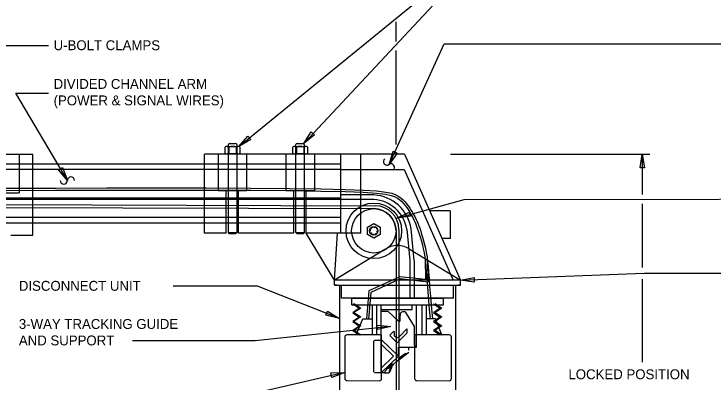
# Model space of a CAD drawing. Extents: x 1299104.6 to 1299141.4, y 239713.3 to 239735.3.
# Drawn here: x 1299120.38 to 1299128.87, y 239725.82 to 239730.29 of the extents above; entities that cross this region are included whole.
import ezdxf

# ---------------------------------------------------------------- set-up
doc = ezdxf.new("R2010")
doc.units = 0
for name, color, linetype in [('Default', 7, 'Continuous'), ('DIM TXT', 7, 'Continuous'), ('Level 3', 7, 'Continuous'), ('Level 6', 7, 'Continuous'), ('Level 8', 7, 'Continuous')]:
    doc.layers.add(name, color=color, linetype=linetype)

# ---------------------------------------------------------------- blocks, each defined once
blk = doc.blocks.new('SPRING')
at = {"layer": 'Default'}
for p, q in [((-0.4, 4), (0.8, 3.2)), ((0.8, 3.2), (-0.4, 2.4)), ((-0.4, 2.4), (0.8, 1.6)), ((0.8, 1.6), (-0.4, 0.8)), ((-0.4, 0.8), (0.8, 0))]:
    blk.add_line(p, q, dxfattribs=at)
blk = doc.blocks.new('HBOLT06T')
at = {"layer": 'Default'}
blk.add_lwpolyline([(0, 2.6), (2.25, 1.3), (2.25, -1.3), (0, -2.6), (-2.25, -1.3), (-2.25, 1.3)], close=True, dxfattribs=at)
blk.add_circle((0, 0), 1.5, dxfattribs=at)
for start, end in [(159.2494, 186.8604), (113.1597, 137.2755), (66.2738, 91.4347), (25.0164, 44.5428), (340.6969, 5.1062), (206.8165, 228.1121), (247.7162, 270.4735), (295.5824, 320.2457)]:
    blk.add_arc((0, 0), 1.27, start, end, dxfattribs=at)
blk = doc.blocks.new('BOLTS')
at = {"layer": 'Default'}
for p, q in [((-1.1, 17.81), (1.1, 17.81)), ((-1.95, 16.76), (1.95, 16.76)), ((-1.5, 0), (-1.5, 17.41)), ((-1.3, 16.52), (-1.3, 14.31)), ((1.3, 16.52), (1.3, 14.31)), ((1.5, 17.41), (1.5, 0)), ((1.95, 14.07), (-1.95, 14.07)), ((-1.5, -14.24), (-1.5, 0)), ((1.5, 0), (1.5, -14.24)), ((-1.5, -14.24), (1.5, -14.24)), ((-1.1, -14.64), (-1.5, -14.24)), ((1.1, -14.64), (-1.1, -14.64)), ((1.5, -14.24), (1.1, -14.64))]:
    blk.add_line(p, q, dxfattribs=at)
for points in [[(-2.6, 14.31), (-2.6, 16.52)], [(2.6, 16.52), (2.6, 14.31)]]:
    blk.add_lwpolyline(points, dxfattribs=at)
for centre, radius, start, end in [((-1.1, 17.41), 0.4, 90, 180), ((1.1, 17.41), 0.4, 0, 90), ((-1.95, 15.76), 1, 49.4687, 130.5313), ((0, 13.12), 3.64, 69.0802, 110.9198), ((1.95, 15.76), 1, 49.4687, 130.5314), ((-1.95, 15.07), 1, 229.4687, 310.5314), ((0, 17.71), 3.64, 249.0802, 290.9198), ((1.95, 15.07), 1, 229.4687, 310.5313)]:
    blk.add_arc(centre, radius, start, end, dxfattribs=at)

msp = doc.modelspace()

# ---------------------------------------------------------------- linework, layer by layer
at = {"layer": 'Level 3'}
for p, q in [((1299118.1826, 239728.5854), (1299120.6126, 239728.5854)), ((1299120.4495, 239728.5854), (1299120.4495, 239728.1129)), ((1299120.6126, 239727.5999), (1299120.6126, 239728.5854)), ((1299122.697, 239728.4639), (1299122.697, 239728.5854)), ((1299125.127, 239728.5854), (1299122.697, 239728.5854)), ((1299122.8625, 239728.5854), (1299122.8625, 239728.1399)), ((1299123.2093, 239728.5854), (1299123.2093, 239728.1399)), ((1299123.686, 239728.5854), (1299123.686, 239728.1399)), ((1299124.0328, 239728.5854), (1299124.0328, 239728.1399)), ((1299124.3548, 239727.6269), (1299124.3548, 239728.5854)), ((1299124.5978, 239727.6269), (1299124.5978, 239728.5854)), ((1299125.127, 239728.5854), (1299125.8054, 239727.0532)), ((1299122.697, 239728.4639), (1299120.6126, 239728.4639)), ((1299122.697, 239727.6269), (1299122.697, 239728.4639)), ((1299120.098, 239728.1129), (1299120.4495, 239728.1129)), ((1299123.2093, 239728.1399), (1299122.8625, 239728.1399)), ((1299122.9616, 239727.6269), (1299122.9616, 239728.1399)), ((1299123.1101, 239727.6269), (1299123.1101, 239728.1399)), ((1299124.0328, 239728.1399), (1299123.686, 239728.1399)), ((1299123.7851, 239727.6269), (1299123.7851, 239728.1399)), ((1299123.9336, 239728.1399), (1299123.7851, 239728.1399)), ((1299123.9336, 239727.6269), (1299123.9336, 239728.1399)), ((1299125.6813, 239727.8955), (1299125.4324, 239727.8955)), ((1299125.6845, 239727.5594), (1299125.6845, 239727.8969)), ((1299124.3548, 239727.8159), (1299122.697, 239727.8159)), ((1299122.697, 239727.7484), (1299120.6126, 239727.7484)), ((1299124.3548, 239727.7484), (1299122.697, 239727.7484)), ((1299123.9336, 239727.7484), (1299123.7851, 239727.7484)), ((1299120.348, 239727.5999), (1299120.6126, 239727.5999)), ((1299122.9616, 239727.6269), (1299122.697, 239727.6269)), ((1299123.7851, 239727.6269), (1299123.1101, 239727.6269)), ((1299124.2772, 239727.0532), (1299123.9336, 239727.6269)), ((1299124.5978, 239727.6269), (1299123.9336, 239727.6269)), ((1299124.2772, 239727.0532), (1299124.315, 239727.6269)), ((1299125.6845, 239727.5594), (1299125.5813, 239727.5594)), ((1299124.8873, 239727.4277), (1299124.2772, 239727.0532)), ((1299125.1953, 239727.4277), (1299125.8054, 239727.0532)), ((1299125.2438, 239727.2948), (1299125.2438, 239726.8346)), ((1299124.2772, 239726.9924), (1299124.2772, 239727.0532)), ((1299125.8054, 239727.0532), (1299124.2772, 239727.0532)), ((1299124.2772, 239726.9924), (1299125.8054, 239726.9924)), ((1299124.3042, 239726.9924), (1299124.2772, 239726.9924)), ((1299124.3359, 239726.9924), (1299124.3359, 239725.2509)), ((1299124.3359, 239726.9924), (1299125.7467, 239726.9924)), ((1299124.3602, 239726.8358), (1299124.3602, 239726.9924)), ((1299125.7224, 239726.8358), (1299125.7224, 239726.9924)), ((1299125.7467, 239726.9924), (1299125.7467, 239725.2509)), ((1299125.8054, 239726.9924), (1299125.7784, 239726.9924)), ((1299125.8054, 239726.9924), (1299125.8054, 239727.0532)), ((1299125.7224, 239726.8358), (1299124.3602, 239726.8358)), ((1299124.4856, 239726.7536), (1299124.4856, 239726.8346)), ((1299124.4856, 239726.8346), (1299125.6007, 239726.8346)), ((1299125.6007, 239726.7536), (1299125.6007, 239726.8346)), ((1299124.4856, 239726.7536), (1299125.6007, 239726.7536)), ((1299124.7343, 239726.7536), (1299124.7343, 239726.3904)), ((1299124.7883, 239726.7536), (1299124.7883, 239726.3904)), ((1299124.842, 239726.6996), (1299124.842, 239726.7536)), ((1299124.8433, 239725.9301), (1299124.8433, 239726.7536)), ((1299125.22, 239726.6996), (1299125.22, 239726.7536)), ((1299125.274, 239726.2406), (1299125.274, 239726.7536)), ((1299125.3355, 239726.7536), (1299125.3355, 239726.3904)), ((1299125.3895, 239726.7536), (1299125.3895, 239726.3904)), ((1299124.842, 239726.6996), (1299125.22, 239726.6996)), ((1299124.927, 239726.6726), (1299124.8433, 239726.6726)), ((1299124.927, 239726.6726), (1299125.0594, 239726.555)), ((1299125.247, 239726.4944), (1299125.1501, 239726.6485)), ((1299124.5417, 239726.3904), (1299124.6208, 239726.5839)), ((1299124.6208, 239726.5839), (1299124.7343, 239726.5839)), ((1299125.0728, 239726.561), (1299125.0728, 239726.6371)), ((1299125.503, 239726.5839), (1299125.3895, 239726.5839)), ((1299125.5821, 239726.3904), (1299125.503, 239726.5839)), ((1299125.247, 239726.2676), (1299125.247, 239726.4944)), ((1299124.8481, 239726.3904), (1299124.4285, 239726.3904)), ((1299124.8481, 239725.8613), (1299124.8481, 239726.3904)), ((1299124.9521, 239726.3914), (1299124.9924, 239726.433)), ((1299124.9924, 239726.433), (1299125.0005, 239726.433)), ((1299125.0005, 239726.433), (1299125.0005, 239726.3856)), ((1299125.0462, 239726.3003), (1299125.1553, 239726.4131)), ((1299125.0651, 239726.3703), (1299125.1562, 239726.4644)), ((1299125.1562, 239726.4644), (1299125.1553, 239726.4131)), ((1299125.6693, 239726.3904), (1299125.2498, 239726.3904)), ((1299125.2498, 239726.3904), (1299125.2498, 239725.8632)), ((1299124.4015, 239726.3634), (1299124.4015, 239725.8632)), ((1299124.7556, 239725.9382), (1299124.7556, 239726.3135)), ((1299124.8433, 239726.3216), (1299124.7637, 239726.3216)), ((1299124.8433, 239726.3351), (1299125.0526, 239726.1326)), ((1299124.9523, 239726.38), (1299125.0348, 239726.3002)), ((1299125.6963, 239725.8613), (1299125.6963, 239726.3634)), ((1299124.8433, 239726.2788), (1299124.9944, 239726.1326)), ((1299125.0526, 239726.2406), (1299125.274, 239726.2406)), ((1299125.0526, 239726.1326), (1299125.0526, 239726.2406)), ((1299125.1795, 239726.2069), (1299125.1795, 239726.2406)), ((1299125.247, 239726.2676), (1299125.274, 239726.2406)), ((1299124.8433, 239725.9865), (1299124.9944, 239726.1326)), ((1299124.8433, 239725.9301), (1299125.0526, 239726.1326)), ((1299124.8433, 239725.9301), (1299124.7637, 239725.9301)), ((1299124.8825, 239725.9301), (1299124.8433, 239725.9301)), ((1299124.8825, 239725.9301), (1299124.9365, 239725.9301)), ((1299124.4284, 239725.8362), (1299124.8209, 239725.8343)), ((1299125.2766, 239725.8362), (1299125.6692, 239725.8343))]:
    msp.add_line(p, q, dxfattribs=at)
for points in [[(1299120.2912, 239728.1707), (1299120.888, 239728.1728), (1299121.5073, 239728.1743), (1299122.1252, 239728.1749), (1299122.7179, 239728.1745), (1299123.2615, 239728.1727), (1299123.732, 239728.1693), (1299124.1117, 239728.1641), (1299124.4063, 239728.1571), (1299124.6278, 239728.1482), (1299124.7881, 239728.1375), (1299124.8994, 239728.1248), (1299124.974, 239728.1099), (1299125.0235, 239728.0922), (1299125.058, 239728.0722), (1299125.0866, 239728.0509), (1299125.1122, 239728.0282), (1299125.1355, 239728.0042), (1299125.1565, 239727.9793), (1299125.1756, 239727.9538), (1299125.193, 239727.9279), (1299125.209, 239727.9021), (1299125.2238, 239727.8765), (1299125.2377, 239727.8512), (1299125.2509, 239727.8258), (1299125.2636, 239727.7999), (1299125.2759, 239727.7732), (1299125.2878, 239727.7453), (1299125.2997, 239727.7159), (1299125.3114, 239727.6846), (1299125.3233, 239727.6511), (1299125.3354, 239727.6149), (1299125.3475, 239727.5759), (1299125.3595, 239727.5342), (1299125.371, 239727.4896), (1299125.3818, 239727.4422), (1299125.3917, 239727.3921), (1299125.4004, 239727.339), (1299125.4077, 239727.2832), (1299125.4136, 239727.2239), (1299125.4188, 239727.1569), (1299125.4245, 239727.077), (1299125.4315, 239726.9789), (1299125.4409, 239726.8573), (1299125.4537, 239726.7071), (1299125.4653, 239726.5839)], [(1299120.2913, 239728.1437), (1299120.8881, 239728.1458), (1299121.5073, 239728.1473), (1299122.1252, 239728.1479), (1299122.7179, 239728.1475), (1299123.2614, 239728.1457), (1299123.7318, 239728.1423), (1299124.1112, 239728.1371), (1299124.4054, 239728.1301), (1299124.6263, 239728.1213), (1299124.7857, 239728.1106), (1299124.8952, 239728.0981), (1299124.9668, 239728.0838), (1299125.0121, 239728.0676), (1299125.0431, 239728.0497), (1299125.0695, 239728.0299), (1299125.0936, 239728.0086), (1299125.1154, 239727.9861), (1299125.1354, 239727.9625), (1299125.1536, 239727.9381), (1299125.1703, 239727.9133), (1299125.1858, 239727.8882), (1299125.2003, 239727.8632), (1299125.2139, 239727.8385), (1299125.2268, 239727.8136), (1299125.2392, 239727.7883), (1299125.2512, 239727.7622), (1299125.2629, 239727.735), (1299125.2745, 239727.7061), (1299125.2861, 239727.6754), (1299125.2978, 239727.6423), (1299125.3097, 239727.6066), (1299125.3216, 239727.5682), (1299125.3334, 239727.5271), (1299125.3447, 239727.4832), (1299125.3554, 239727.4366), (1299125.3651, 239727.3872), (1299125.3737, 239727.3351), (1299125.3809, 239727.2801), (1299125.3867, 239727.2215), (1299125.3919, 239727.1549), (1299125.3975, 239727.075), (1299125.4046, 239726.9769), (1299125.414, 239726.8551), (1299125.4269, 239726.7046), (1299125.4382, 239726.5839)], [(1299125.3778, 239727.3037), (1299125.3809, 239727.0623), (1299125.0713, 239727.0967), (1299124.693, 239726.9249), (1299124.6645, 239726.5839)], [(1299125.4048, 239727.3057), (1299125.4083, 239727.0321), (1299125.0757, 239727.069), (1299124.7186, 239726.9069), (1299124.6916, 239726.5839)]]:
    msp.add_lwpolyline(points, dxfattribs=at)
for centre, radius, start, end in [((1299124.7544, 239727.6536), 0.27, 0, 89.81051), ((1299125.0413, 239727.1931), 0.2806, 56.70764, 123.29236), ((1299125.113, 239726.6321), 0.0405, 23.81865, 187.13136), ((1299125.0647, 239726.561), 0.0081, 228.36646, 0), ((1299124.4285, 239726.3634), 0.027, 90, 180), ((1299124.9579, 239726.3858), 0.0081, 135.93919, 225.93919), ((1299125.6693, 239726.3634), 0.027, 0, 90), ((1299124.7637, 239726.3135), 0.0081, 90, 180), ((1299125.0382, 239726.4009), 0.0407, 202.08979, 311.37571), ((1299125.0404, 239726.306), 0.0081, 225.93919, 315.93919), ((1299124.4285, 239725.8632), 0.027, 180, 269.7176), ((1299124.8211, 239725.8613), 0.027, 269.7176, 0), ((1299125.2768, 239725.8632), 0.027, 180, 269.7176), ((1299125.6693, 239725.8613), 0.027, 269.7176, 0)]:
    msp.add_arc(centre, radius, start, end, dxfattribs=at)
for points in [[(1299125.031, 239726.0677), (1299125.1585, 239726.1631), (1299125.1795, 239726.2069), (1299124.9642, 239726.0243), (1299125.1792, 239726.1826)], [(1299125.031, 239726.0685), (1299124.9707, 239726.0119), (1299124.9525, 239725.9826), (1299124.9409, 239725.9543), (1299124.9365, 239725.9301), (1299125.0007, 239726.0403), (1299124.9365, 239725.9301)], [(1299124.8825, 239725.9301), (1299124.9337, 239726.0166), (1299125.031, 239726.0677), (1299124.8825, 239725.9301), (1299124.9798, 239726.0477)]]:
    msp.add_open_spline(points, degree=3, dxfattribs=at)
at = {"layer": 'Level 6'}
for p, q in [((1299120.6126, 239728.4639), (1299118.9548, 239728.4639)), ((1299124.3548, 239728.4639), (1299122.697, 239728.4639)), ((1299120.6126, 239728.3964), (1299118.9548, 239728.3964)), ((1299122.697, 239728.3964), (1299120.6126, 239728.3964)), ((1299124.3548, 239728.3964), (1299122.697, 239728.3964)), ((1299124.3548, 239728.3964), (1299125.1221, 239728.3964)), ((1299125.1221, 239728.3964), (1299125.7168, 239727.0532)), ((1299124.7549, 239728.0887), (1299124.3548, 239728.0887)), ((1299124.3548, 239728.0482), (1299118.9548, 239728.0482)), ((1299124.3548, 239728.0347), (1299118.9548, 239728.0347)), ((1299124.7549, 239728.0347), (1299124.3548, 239728.0347)), ((1299117.9141, 239727.98), (1299124.7722, 239727.9573)), ((1299117.9309, 239727.9462), (1299124.7553, 239727.9236)), ((1299120.6126, 239727.8159), (1299118.9548, 239727.8159)), ((1299122.697, 239727.8159), (1299120.6126, 239727.8159)), ((1299120.6126, 239727.7484), (1299118.9548, 239727.7484)), ((1299125.0582, 239727.6704), (1299125.0582, 239724.762)), ((1299125.1558, 239727.6737), (1299125.1898, 239727.2948)), ((1299125.2438, 239727.2948), (1299125.2066, 239727.6776)), ((1299125.0244, 239727.6536), (1299125.0244, 239724.6609)), ((1299125.1898, 239727.2948), (1299125.1898, 239726.8346))]:
    msp.add_line(p, q, dxfattribs=at)
for radius in [0.3375, 0.27]:
    msp.add_circle((1299124.7544, 239727.6536), radius, dxfattribs=at)
for centre, radius, start, end in [((1299124.7282, 239727.6056), 0.4838, 8.5622, 86.82966), ((1299124.7254, 239727.5989), 0.4368, 9.86195, 86.12318), ((1299124.7713, 239727.6704), 0.2869, 0, 89.81051)]:
    msp.add_arc(centre, radius, start, end, dxfattribs=at)
at = {"layer": 'Level 8'}
for p, q in [((1299125.0244, 239729.9525), (1299125.0244, 239730.1923)), ((1299125.0244, 239728.7033), (1299125.0244, 239729.8445)), ((1299125.6871, 239728.5854), (1299128.1042, 239728.5854)), ((1299128.0143, 239728.5854), (1299128.0143, 239728.0942)), ((1299128.0143, 239727.9795), (1299128.0143, 239727.2073)), ((1299128.0143, 239727.0667), (1299128.0143, 239726.0593))]:
    msp.add_line(p, q, dxfattribs=at)
for points in [[(1299123.1134, 239728.6774), (1299123.1134, 239728.6774), (1299126.2852, 239731.2629), (1299132.0119, 239731.2629)], [(1299123.9042, 239728.7118), (1299126.2852, 239731.2629), (1299132.0486, 239731.2629)], [(1299119.5029, 239728.6996), (1299119.5029, 239728.6996), (1299120.1241, 239729.9022), (1299120.793, 239729.9022)], [(1299120.2704, 239728.7139), (1299120.1241, 239729.9022), (1299120.8021, 239729.9022)], [(1299124.9394, 239728.4584), (1299125.6073, 239729.9251), (1299132.0486, 239729.9251)], [(1299121.0327, 239728.2641), (1299120.4081, 239729.3245), (1299120.8021, 239729.3245)], [(1299125.0338, 239727.8061), (1299125.8498, 239728.0327), (1299132.0486, 239728.042)], [(1299125.8054, 239727.0532), (1299128.0369, 239727.1383), (1299132.0486, 239727.1383)], [(1299124.3359, 239726.5906), (1299123.3425, 239726.9822), (1299122.3177, 239726.9822)], [(1299124.9624, 239726.4929), (1299123.3141, 239726.3196), (1299121.8229, 239726.3185), (1299121.8229, 239726.3185)], [(1299124.4015, 239725.9331), (1299122.685, 239725.5375), (1299121.5664, 239725.5375), (1299121.5664, 239725.5375)]]:
    msp.add_lwpolyline(points, dxfattribs=at)
for points in [[(1299123.9948, 239728.8545), (1299124.0354, 239728.8183), (1299123.9042, 239728.7118)], [(1299123.2242, 239728.8047), (1299123.2591, 239728.763), (1299123.1137, 239728.6767)], [(1299124.9902, 239728.619), (1299125.0388, 239728.5947), (1299124.9397, 239728.4577)], [(1299128.0415, 239728.4186), (1299127.9871, 239728.4186), (1299128.0143, 239728.5854)], [(1299120.9252, 239728.3936), (1299120.972, 239728.4212), (1299121.0333, 239728.2637)], [(1299125.185, 239727.8818), (1299125.2012, 239727.8299), (1299125.0338, 239727.8061)], [(1299125.9712, 239727.0859), (1299125.973, 239727.0316), (1299125.8054, 239727.0532)], [(1299124.1714, 239726.6295), (1299124.1923, 239726.6797), (1299124.3359, 239726.5906)], [(1299124.7979, 239726.4542), (1299124.7941, 239726.5084), (1299124.9624, 239726.4929)], [(1299124.2429, 239725.8748), (1299124.2326, 239725.9282), (1299124.4015, 239725.9331)]]:
    msp.add_lwpolyline(points, close=True, dxfattribs=at)
for centre, start, end in [((1299124.9144, 239728.4934), 125.51652, 305.51652), ((1299124.9644, 239728.4234), 305.51652, 125.51652), ((1299120.9896, 239728.2637), 180.49657, 0.49657), ((1299121.0757, 239728.2645), 0.49657, 180.49657)]:
    msp.add_arc(centre, 0.043, start, end, dxfattribs=at)

# ---------------------------------------------------------------- block references
at = {"layer": 'Level 3'}
for name, p, xscale, yscale in [('BOLTS', (1299123.0386, 239728.1129), 0.03374999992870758, 0.0337499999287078), ('BOLTS', (1299123.8599, 239728.1129), 0.03374999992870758, 0.0337499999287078), ('HBOLT06T', (1299124.7544, 239727.6536), 0.03374999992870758, 0.0337499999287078), ('SPRING', (1299124.5261, 239726.498), 0.0674999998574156, 0.06749999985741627), ('SPRING', (1299124.5407, 239726.5), 0.0674999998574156, 0.06749999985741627), ('SPRING', (1299125.5067, 239726.4972), 0.0674999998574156, 0.06749999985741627), ('SPRING', (1299125.5275, 239726.5), 0.0674999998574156, 0.06749999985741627), ('SPRING', (1299124.5261, 239726.3901), 0.0674999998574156, 0.06749999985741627), ('SPRING', (1299124.5407, 239726.3922), 0.0674999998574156, 0.06749999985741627), ('SPRING', (1299125.5066, 239726.3894), 0.0674999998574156, 0.06749999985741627), ('SPRING', (1299125.5274, 239726.3922), 0.0674999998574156, 0.06749999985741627)]:
    msp.add_blockref(name, p, dxfattribs=dict(at, xscale=xscale, yscale=yscale))

# ---------------------------------------------------------------- texts
at = {"layer": 'DIM TXT'}
for s, p in [('U-BOLT CLAMPS', (1299120.8659, 239729.8464)), ('DIVIDED CHANNEL ARM ', (1299120.8659, 239729.3768)), ('(POWER & SIGNAL WIRES)', (1299120.8659, 239729.1768)), ('DISCONNECT UNIT', (1299120.444, 239726.9261)), ('3-WAY TRACKING GUIDE ', (1299120.444, 239726.4631)), ('AND SUPPORT', (1299120.444, 239726.2631)), ('LOCKED POSITION', (1299127.1177, 239725.8524))]:
    msp.add_text(s, height=0.12, dxfattribs=at).set_placement(p)

doc.saveas('drawing.dxf')
